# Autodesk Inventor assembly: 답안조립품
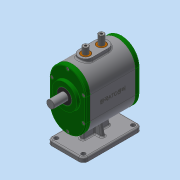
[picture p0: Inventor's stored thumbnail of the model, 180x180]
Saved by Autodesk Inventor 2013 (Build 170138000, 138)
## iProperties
Created: 2018-10
Part Number: 답안조립품
Document SubType Name: Assembly
Designer: Administrator
Author: Administrator
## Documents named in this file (15)
- C:\Users\Administrator\Desktop\381007V1061\답안조립품.iam
- C:\Users\Administrator\Desktop\381007V1061\본체.ipt
- C:\Users\Administrator\Desktop\381007V1061\가변스프링1.ipt
- C:\Users\Administrator\Desktop\381007V1061\가변스프링2.ipt
- C:\Users\Administrator\Desktop\381007V1061\뒤커버.ipt
- C:\Users\Administrator\Desktop\381007V1061\메인축.ipt
- C:\Users\Administrator\Desktop\381007V1061\베어링 608.ipt
- C:\Users\Administrator\Desktop\381007V1061\베어링 6003.ipt
- C:\Users\Administrator\Desktop\381007V1061\볼트 M4.ipt
- C:\Users\Administrator\Desktop\381007V1061\부시.ipt
- C:\Users\Administrator\Desktop\381007V1061\서브축.ipt
- C:\Users\Administrator\Desktop\381007V1061\슬라이더.ipt
- C:\Users\Administrator\Desktop\381007V1061\앞커버.ipt
- C:\Users\Administrator\Desktop\381007V1061\오일실 8 22 7.ipt
- C:\Users\Administrator\Desktop\381007V1061\오일실 17 32 8.ipt
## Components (2 placed, 2 different names)
1. 가변스프링2:1
2. 가변스프링1:1
